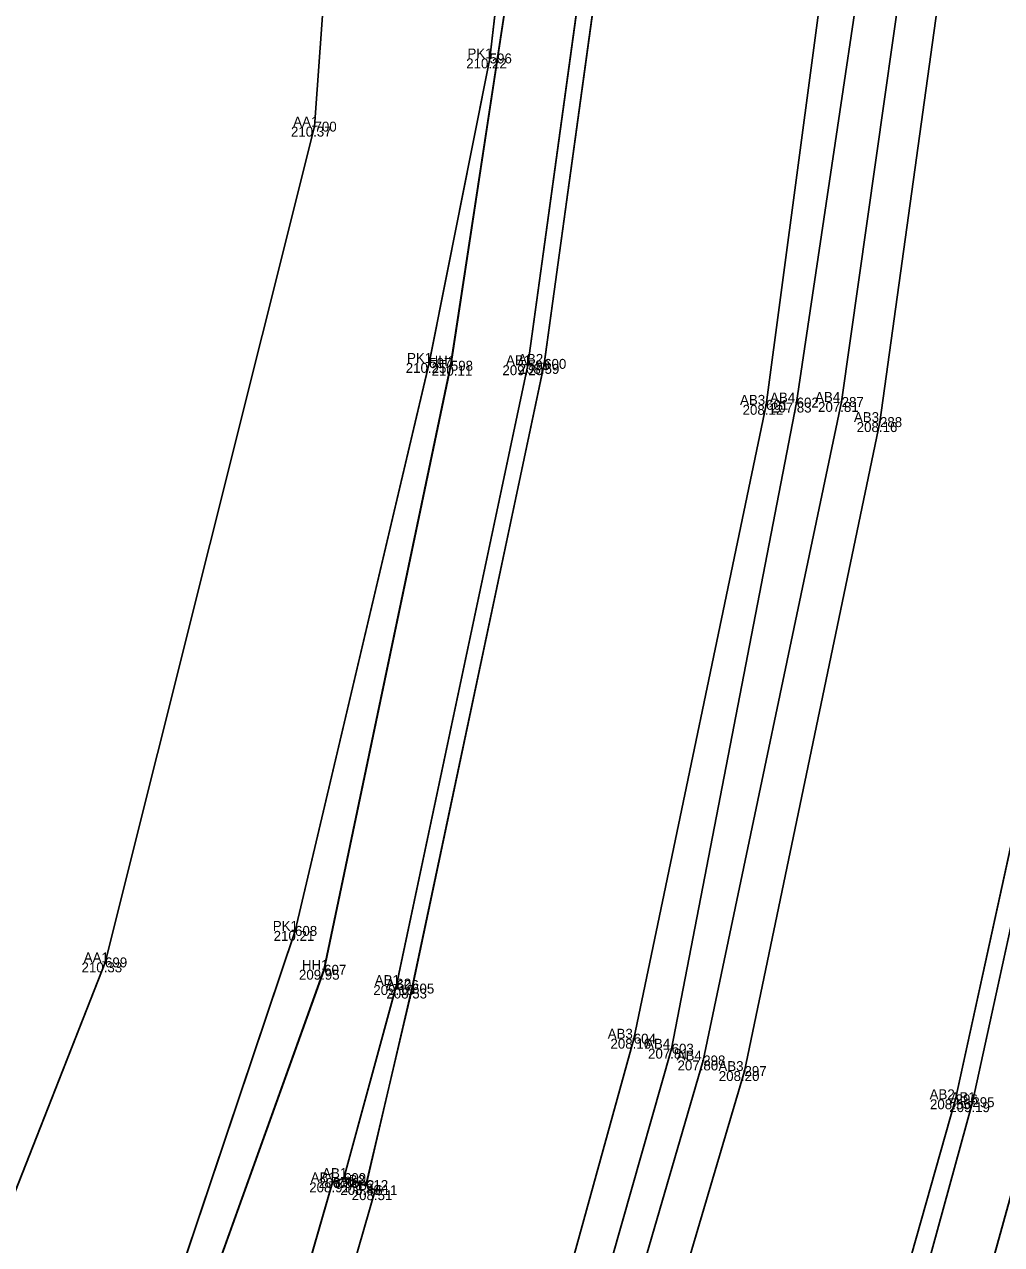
# Model space of a CAD drawing. Extents: x -263091 to -262565, y -1238731 to -1237092.
# Drawn here: x -262851.71 to -262832.04, y -1238071.97 to -1238047.41 of the extents above; entities that cross this region are included whole.
import ezdxf

# ---------------------------------------------------------------- set-up
doc = ezdxf.new("R2010")
doc.units = 0
for name, color, linetype in [('01_Hrana_betónu', 7, 'Continuous'), ('02_Oplotenie', 7, 'Continuous'), ('03_Asfalt', 7, 'Continuous'), ('05_Hrana_terénu', 7, 'Continuous'), ('09_Múrik', 7, 'Continuous'), ('Groma (21)', 7, 'Continuous'), ('Groma (22)', 7, 'Continuous'), ('Groma (23)', 7, 'Continuous'), ('Groma (24)', 7, 'Continuous'), ('U003_Betónové_múriky', 7, 'Continuous'), ('U003_Betónové_panely', 7, 'Continuous'), ('U003_Zeleň_mimo', 7, 'Continuous'), ('U003_Zeleň_vnútro', 7, 'Continuous'), ('U003_Zeleň_zatrávňovač', 7, 'Continuous'), ('U005_Betóny_prídavné', 7, 'Continuous')]:
    doc.layers.add(name, color=color, linetype=linetype)

msp = doc.modelspace()

# ---------------------------------------------------------------- linework, layer by layer
at = {"layer": '01_Hrana_betónu'}
for points in [[(-262903.088, -1238238.797), (-262890.817, -1238204.479), (-262885.468, -1238189.492), (-262878.003, -1238168.56), (-262870.455, -1238147.513), (-262864.947, -1238132.168), (-262859.037, -1238116.651), (-262848.977, -1238095.826), (-262842.353, -1238078.361), (-262839.446, -1238067.823), (-262836.783, -1238055.069), (-262834.905, -1238040.999), (-262833.763, -1238025.462), (-262832.297, -1238000.555), (-262831.13, -1237981.111), (-262829.791, -1237958.391), (-262828.651, -1237937.03), (-262828.571, -1237935.876)], [(-262827.762, -1237935.927), (-262827.853, -1237937.062), (-262829.049, -1237958.415), (-262830.305, -1237981.211), (-262831.433, -1238000.629), (-262832.987, -1238025.43), (-262834.086, -1238041.027), (-262836.169, -1238055.023), (-262838.684, -1238068.024), (-262841.681, -1238078.569), (-262848.285, -1238096.308), (-262858.162, -1238116.913), (-262863.876, -1238132.122), (-262869.919, -1238147.692), (-262877.244, -1238168.638), (-262884.69, -1238189.67), (-262901.991, -1238238.762)], [(-262827.034, -1237935.973), (-262827.072, -1237937.036), (-262828.491, -1237960.168), (-262829.643, -1237980.454), (-262830.754, -1238002.123), (-262832.4, -1238026.024), (-262833.369, -1238041.644), (-262835.263, -1238055.011), (-262838.048, -1238068.261), (-262841.826, -1238081.232), (-262846.645, -1238094.136), (-262857.777, -1238117.273), (-262863.292, -1238131.948), (-262884.082, -1238190.299), (-262901.352, -1238238.742)], [(-262900.376, -1238238.711), (-262890.192, -1238209.46), (-262883.463, -1238190.564), (-262868.512, -1238148.877), (-262862.514, -1238132.276), (-262857.014, -1238117.706), (-262845.846, -1238094.561), (-262841.058, -1238081.49), (-262837.218, -1238068.474), (-262834.492, -1238055.416), (-262832.606, -1238041.772), (-262831.509, -1238026.143), (-262830.024, -1238002.24), (-262828.826, -1237980.518), (-262827.576, -1237960.277), (-262826.117, -1237937.218), (-262826.079, -1237936.033)], [(-262908.762, -1238238.978), (-262904.818, -1238227.708), (-262897.756, -1238208.088), (-262895.676, -1238202.213), (-262890.59, -1238187.74), (-262883.178, -1238166.691), (-262875.605, -1238145.524), (-262870.177, -1238130.111), (-262864.546, -1238115.411), (-262863.698, -1238113.971), (-262862.86, -1238112.208), (-262862.02, -1238109.736), (-262852.529, -1238091.409), (-262847.756, -1238078.518), (-262845.507, -1238070.714), (-262845.277, -1238070.627)], [(-262907.715, -1238238.945), (-262903.959, -1238228.072), (-262896.871, -1238208.378), (-262894.873, -1238202.609), (-262889.743, -1238188.028), (-262882.328, -1238167.085), (-262874.744, -1238145.867), (-262869.274, -1238130.427), (-262863.367, -1238114.899), (-262851.765, -1238091.959), (-262846.929, -1238078.783), (-262844.647, -1238070.871), (-262844.833, -1238070.767)]]:
    msp.add_lwpolyline(points, dxfattribs=at)
at = {"layer": '02_Oplotenie'}
msp.add_lwpolyline([(-262912.451, -1238238.295), (-262908.254, -1238226.663), (-262901.526, -1238207.942), (-262898.552, -1238199.602), (-262894.22, -1238186.327), (-262886.794, -1238165.648), (-262879.297, -1238144.201), (-262873.976, -1238128.814), (-262867.141, -1238113.572), (-262855.316, -1238089.931), (-262850.675, -1238078.807), (-262846.261, -1238065.654), (-262843.56, -1238054.226), (-262842.344, -1238048.099), (-262841.445, -1238040.349), (-262840.733, -1238030.077), (-262839.013, -1238000.384), (-262838.353, -1237989.712), (-262835.178, -1237935.879)], dxfattribs=at)
at = {"layer": '03_Asfalt'}
msp.add_lwpolyline([(-262912.678, -1238239.103), (-262913.356, -1238239.285), (-262915.717, -1238239.279), (-262916.328, -1238238.784), (-262916.575, -1238236.319), (-262915.768, -1238233.661), (-262912.404, -1238225.097), (-262904.805, -1238205.606), (-262896.687, -1238184.948), (-262888.478, -1238163.929), (-262880.124, -1238142.63), (-262874.65, -1238128.675), (-262868.549, -1238113.075), (-262858.861, -1238088.481), (-262853.132, -1238074.038), (-262850.084, -1238066.288), (-262845.869, -1238049.471), (-262845.094, -1238038.662), (-262844.346, -1238028.542), (-262842.599, -1238000.955), (-262841.603, -1237985.168), (-262838.824, -1237943.888), (-262838.24, -1237934.633), (-262838.283, -1237933.488)], dxfattribs=at)
at = {"layer": '05_Hrana_terénu'}
for points in [[(-262835.062, -1237935.275), (-262834.86, -1237936.333), (-262838.087, -1237989.633), (-262838.484, -1238000.332), (-262840.387, -1238030.181), (-262840.991, -1238040.253), (-262843.126, -1238054.282), (-262845.675, -1238066.436), (-262850.413, -1238079.623), (-262854.798, -1238090.209), (-262863.856, -1238108.78), (-262866.643, -1238114.502), (-262872.333, -1238129.41), (-262877.981, -1238144.625), (-262885.616, -1238166.033), (-262893.121, -1238186.676), (-262898.244, -1238201.149), (-262900.554, -1238208.001), (-262907.375, -1238226.781), (-262911.85, -1238238.364), (-262912.678, -1238239.103)], [(-262849.564, -1238120.544), (-262839.894, -1238095.583), (-262835.301, -1238083.403), (-262831.402, -1238069.334), (-262828.632, -1238056.516), (-262826.436, -1238041.83), (-262825.08, -1238026.06), (-262823.863, -1238001.967), (-262822.633, -1237980.847), (-262821.298, -1237960.54), (-262820.334, -1237939.047), (-262819.871, -1237937.657)]]:
    msp.add_lwpolyline(points, dxfattribs=at)
at = {"layer": '09_Múrik'}
for points in [[(-262845.277, -1238070.627), (-262844.218, -1238066.744), (-262841.577, -1238054.272), (-262839.647, -1238040.289), (-262838.75, -1238030.675), (-262836.979, -1238000.411), (-262836.237, -1237989.843), (-262834.391, -1237956.949), (-262833.055, -1237935.594)], [(-262844.833, -1238070.767), (-262843.906, -1238066.814), (-262841.249, -1238054.245), (-262839.306, -1238040.158), (-262838.493, -1238030.433), (-262836.614, -1238000.277), (-262836.049, -1237989.856), (-262833.996, -1237956.678), (-262832.67, -1237935.618)], [(-262840.924, -1238094.827), (-262836.941, -1238083.068), (-262832.969, -1238069.042), (-262830.214, -1238056.416), (-262828.063, -1238041.942), (-262826.83, -1238026.465), (-262825.494, -1238001.855), (-262824.316, -1237980.84), (-262823.031, -1237960.337), (-262821.719, -1237936.336)], [(-262840.6, -1238094.732), (-262836.43, -1238082.967), (-262832.633, -1238069.1), (-262829.86, -1238056.421), (-262827.688, -1238042.018), (-262826.338, -1238026.448), (-262825.108, -1238001.872), (-262823.89, -1237980.741), (-262822.602, -1237960.47), (-262821.253, -1237936.39)]]:
    msp.add_lwpolyline(points, dxfattribs=at)
at = {"layer": 'Groma (21)'}
for centre in [(-262842.344, -1238048.099), (-262845.869, -1238049.471), (-262843.56, -1238054.226), (-262841.249, -1238054.245), (-262843.126, -1238054.282), (-262841.577, -1238054.272), (-262836.783, -1238055.069), (-262836.169, -1238055.023), (-262835.263, -1238055.011), (-262834.492, -1238055.416), (-262846.261, -1238065.654), (-262850.084, -1238066.288), (-262845.675, -1238066.436), (-262844.218, -1238066.744), (-262843.906, -1238066.814), (-262839.446, -1238067.823), (-262838.684, -1238068.024), (-262838.048, -1238068.261), (-262837.218, -1238068.474), (-262832.969, -1238069.042), (-262832.633, -1238069.1), (-262845.507, -1238070.714), (-262845.277, -1238070.627), (-262844.833, -1238070.767), (-262844.647, -1238070.871)]:
    msp.add_circle(centre, 0.01, dxfattribs=at)
at = {"layer": 'U003_Betónové_múriky'}
for points in [[(-262834.39, -1237956.95), (-262833.05, -1237935.59), (-262832.67, -1237935.62), (-262834, -1237956.68), (-262836.05, -1237989.86), (-262836.61, -1238000.28), (-262838.49, -1238030.43), (-262839.31, -1238040.16), (-262841.25, -1238054.25), (-262843.91, -1238066.81), (-262844.83, -1238070.77), (-262845.28, -1238070.63), (-262844.22, -1238066.74), (-262841.58, -1238054.27), (-262839.65, -1238040.29), (-262838.75, -1238030.68), (-262836.98, -1238000.41), (-262836.24, -1237989.84)], [(-262821.25, -1237936.39), (-262822.6, -1237960.47), (-262823.89, -1237980.74), (-262825.11, -1238001.87), (-262826.34, -1238026.45), (-262827.69, -1238042.02), (-262829.86, -1238056.42), (-262832.63, -1238069.1), (-262836.43, -1238082.97), (-262840.6, -1238094.73), (-262840.92, -1238094.83), (-262836.94, -1238083.07), (-262832.97, -1238069.04), (-262830.21, -1238056.42), (-262828.06, -1238041.94), (-262826.83, -1238026.47), (-262825.49, -1238001.86), (-262824.32, -1237980.84), (-262823.03, -1237960.34), (-262821.72, -1237936.34)]]:
    msp.add_lwpolyline(points, close=True, dxfattribs=at)
for points in [[(-262836.24, -1237989.84), (-262834.39, -1237956.95), (-262833.05, -1237935.59), (-262832.67, -1237935.62), (-262834, -1237956.68), (-262836.05, -1237989.86), (-262836.61, -1238000.28), (-262838.49, -1238030.43), (-262839.31, -1238040.16), (-262841.25, -1238054.25), (-262843.91, -1238066.81), (-262844.83, -1238070.77), (-262845.28, -1238070.63), (-262844.22, -1238066.74), (-262841.58, -1238054.27), (-262839.65, -1238040.29), (-262838.75, -1238030.68), (-262836.98, -1238000.41), (-262836.24, -1237989.84)], [(-262821.72, -1237936.34), (-262821.25, -1237936.39), (-262822.6, -1237960.47), (-262823.89, -1237980.74), (-262825.11, -1238001.87), (-262826.34, -1238026.45), (-262827.69, -1238042.02), (-262829.86, -1238056.42), (-262832.63, -1238069.1), (-262836.43, -1238082.97), (-262840.6, -1238094.73), (-262840.92, -1238094.83), (-262836.94, -1238083.07), (-262832.97, -1238069.04), (-262830.21, -1238056.42), (-262828.06, -1238041.94), (-262826.83, -1238026.47), (-262825.49, -1238001.86), (-262824.32, -1237980.84), (-262823.03, -1237960.34), (-262821.72, -1237936.34)]]:
    msp.add_lwpolyline(points, dxfattribs=at)
at = {"layer": 'U003_Betónové_panely'}
for points in [[(-262863.7, -1238113.97), (-262862.86, -1238112.21), (-262862.02, -1238109.74), (-262852.53, -1238091.41), (-262847.76, -1238078.52), (-262845.51, -1238070.71), (-262845.28, -1238070.63), (-262844.83, -1238070.77), (-262843.91, -1238066.81), (-262841.25, -1238054.25), (-262839.31, -1238040.16), (-262838.49, -1238030.43), (-262836.61, -1238000.28), (-262836.05, -1237989.86), (-262834, -1237956.68), (-262832.67, -1237935.62), (-262832.64, -1237935.62), (-262832.51, -1237933.84)], [(-262863.7, -1238113.97), (-262862.86, -1238112.21), (-262862.02, -1238109.74), (-262852.53, -1238091.41), (-262847.76, -1238078.52), (-262845.51, -1238070.71), (-262845.28, -1238070.63), (-262844.83, -1238070.77), (-262843.91, -1238066.81), (-262841.25, -1238054.25), (-262839.31, -1238040.16), (-262838.49, -1238030.43), (-262836.61, -1238000.28), (-262836.05, -1237989.86), (-262834, -1237956.68), (-262832.67, -1237935.62), (-262832.64, -1237935.62), (-262832.51, -1237933.84)], [(-262822, -1237934.47), (-262822.23, -1237936.28), (-262821.72, -1237936.34), (-262823.03, -1237960.34), (-262824.32, -1237980.84), (-262825.49, -1238001.86), (-262826.83, -1238026.47), (-262828.06, -1238041.94), (-262830.21, -1238056.42), (-262832.97, -1238069.04), (-262836.94, -1238083.07), (-262840.92, -1238094.83), (-262840.6, -1238094.73), (-262841.76, -1238095.81), (-262851.46, -1238119.84), (-262857.2, -1238134.12), (-262863.32, -1238150.73), (-262871.41, -1238173.11), (-262878.16, -1238192.14), (-262884.61, -1238210.94), (-262889.86, -1238225.24), (-262892.75, -1238232.5), (-262895.19, -1238238.55), (-262900.83, -1238252.4)], [(-262822, -1237934.47), (-262822.23, -1237936.28), (-262821.72, -1237936.34), (-262823.03, -1237960.34), (-262824.32, -1237980.84), (-262825.49, -1238001.86), (-262826.83, -1238026.47), (-262828.06, -1238041.94), (-262830.21, -1238056.42), (-262832.97, -1238069.04), (-262836.94, -1238083.07), (-262840.92, -1238094.83), (-262840.6, -1238094.73), (-262841.76, -1238095.81), (-262851.46, -1238119.84), (-262857.2, -1238134.12), (-262863.32, -1238150.73), (-262871.41, -1238173.11), (-262878.16, -1238192.14), (-262884.61, -1238210.94), (-262889.86, -1238225.24), (-262892.75, -1238232.5), (-262895.19, -1238238.55), (-262900.83, -1238252.4)]]:
    msp.add_lwpolyline(points, dxfattribs=at)
at = {"layer": 'U003_Zeleň_mimo'}
for points in [[(-262868.55, -1238113.08), (-262858.86, -1238088.48), (-262853.13, -1238074.04), (-262850.08, -1238066.29), (-262845.87, -1238049.47), (-262845.09, -1238038.66), (-262844.35, -1238028.54), (-262842.6, -1238000.96), (-262841.6, -1237985.17), (-262838.82, -1237943.89), (-262838.24, -1237934.63)], [(-262836.32, -1237934.59), (-262836.29, -1237935.17), (-262835.06, -1237935.28), (-262835.18, -1237935.88), (-262838.35, -1237989.71), (-262839.01, -1238000.38), (-262840.73, -1238030.08), (-262841.45, -1238040.35), (-262842.34, -1238048.1), (-262843.56, -1238054.23), (-262846.26, -1238065.65), (-262850.68, -1238078.81), (-262855.32, -1238089.93), (-262867.14, -1238113.57)]]:
    msp.add_lwpolyline(points, dxfattribs=at)
at = {"layer": 'U003_Zeleň_vnútro'}
for points in [[(-262849.56, -1238120.54), (-262839.89, -1238095.58), (-262835.3, -1238083.4), (-262831.4, -1238069.33), (-262828.63, -1238056.52), (-262826.44, -1238041.83), (-262825.08, -1238026.06), (-262823.86, -1238001.97), (-262822.63, -1237980.85), (-262821.3, -1237960.54), (-262820.33, -1237939.05), (-262819.87, -1237937.66), (-262819.76, -1237938.03), (-262820.79, -1237960.68), (-262821.84, -1237980.92), (-262823.31, -1238002.11), (-262824.58, -1238026.07), (-262825.82, -1238041.97), (-262827.77, -1238056.55), (-262830.57, -1238069.55), (-262834.59, -1238083.86), (-262839.33, -1238095.84), (-262848.78, -1238120.94)], [(-262849.56, -1238120.54), (-262839.89, -1238095.58), (-262835.3, -1238083.4), (-262831.4, -1238069.33), (-262828.63, -1238056.52), (-262826.44, -1238041.83), (-262825.08, -1238026.06), (-262823.86, -1238001.97), (-262822.63, -1237980.85), (-262821.3, -1237960.54), (-262820.33, -1237939.05), (-262819.87, -1237937.66), (-262819.76, -1237938.03), (-262820.79, -1237960.68), (-262821.84, -1237980.92), (-262823.31, -1238002.11), (-262824.58, -1238026.07), (-262825.82, -1238041.97), (-262827.77, -1238056.55), (-262830.57, -1238069.55), (-262834.59, -1238083.86), (-262839.33, -1238095.84), (-262848.78, -1238120.94)], [(-262867.14, -1238113.57), (-262855.32, -1238089.93), (-262850.68, -1238078.81), (-262846.26, -1238065.65), (-262843.56, -1238054.23), (-262842.34, -1238048.1), (-262841.45, -1238040.35), (-262840.73, -1238030.08), (-262839.01, -1238000.38)], [(-262867.14, -1238113.57), (-262855.32, -1238089.93), (-262850.68, -1238078.81), (-262846.26, -1238065.65), (-262843.56, -1238054.23), (-262842.34, -1238048.1), (-262841.45, -1238040.35), (-262840.73, -1238030.08), (-262839.01, -1238000.38)], [(-262838.48, -1238000.33), (-262840.39, -1238030.18), (-262840.99, -1238040.25), (-262843.13, -1238054.28), (-262845.68, -1238066.44), (-262850.41, -1238079.62), (-262854.8, -1238090.21), (-262863.86, -1238108.78), (-262863.4, -1238109.07), (-262864.42, -1238111.37), (-262865.55, -1238113.22)], [(-262838.48, -1238000.33), (-262840.39, -1238030.18), (-262840.99, -1238040.25), (-262843.13, -1238054.28), (-262845.68, -1238066.44), (-262850.41, -1238079.62), (-262854.8, -1238090.21), (-262863.86, -1238108.78), (-262863.4, -1238109.07), (-262864.42, -1238111.37), (-262865.55, -1238113.22)]]:
    msp.add_lwpolyline(points, dxfattribs=at)
at = {"layer": 'U003_Zeleň_zatrávňovač'}
for points in [[(-262836.98, -1238000.41), (-262838.75, -1238030.68), (-262839.65, -1238040.29), (-262841.58, -1238054.27), (-262844.22, -1238066.74), (-262845.28, -1238070.63), (-262845.51, -1238070.71), (-262847.76, -1238078.52), (-262852.53, -1238091.41), (-262862.02, -1238109.74), (-262863.4, -1238109.07), (-262863.86, -1238108.78), (-262854.8, -1238090.21), (-262850.41, -1238079.62), (-262845.68, -1238066.44), (-262843.13, -1238054.28), (-262840.99, -1238040.25), (-262840.39, -1238030.18), (-262838.48, -1238000.33)], [(-262862.02, -1238109.74), (-262863.4, -1238109.07), (-262863.86, -1238108.78), (-262854.8, -1238090.21), (-262850.41, -1238079.62), (-262845.68, -1238066.44), (-262843.13, -1238054.28), (-262840.99, -1238040.25), (-262840.39, -1238030.18), (-262838.48, -1238000.33)], [(-262836.98, -1238000.41), (-262838.75, -1238030.68), (-262839.65, -1238040.29), (-262841.58, -1238054.27), (-262844.22, -1238066.74), (-262845.28, -1238070.63), (-262845.51, -1238070.71), (-262847.76, -1238078.52), (-262852.53, -1238091.41), (-262862.02, -1238109.74)], [(-262851.46, -1238119.84), (-262841.76, -1238095.81), (-262840.6, -1238094.73), (-262836.43, -1238082.97), (-262832.63, -1238069.1), (-262829.86, -1238056.42), (-262827.69, -1238042.02), (-262826.34, -1238026.45), (-262825.11, -1238001.87)], [(-262823.86, -1238001.97), (-262825.08, -1238026.06), (-262826.44, -1238041.83), (-262828.63, -1238056.52), (-262831.4, -1238069.33), (-262835.3, -1238083.4), (-262839.89, -1238095.58), (-262849.56, -1238120.54)]]:
    msp.add_lwpolyline(points, dxfattribs=at)
at = {"layer": 'U005_Betóny_prídavné'}
for points in [[(-262851.46, -1238119.84), (-262841.76, -1238095.81), (-262840.6, -1238094.73), (-262836.43, -1238082.97), (-262832.63, -1238069.1), (-262829.86, -1238056.42), (-262827.69, -1238042.02), (-262826.34, -1238026.45), (-262825.11, -1238001.87)], [(-262823.86, -1238001.97), (-262825.08, -1238026.06), (-262826.44, -1238041.83), (-262828.63, -1238056.52), (-262831.4, -1238069.33), (-262835.3, -1238083.4), (-262839.89, -1238095.58), (-262849.56, -1238120.54)]]:
    msp.add_lwpolyline(points, dxfattribs=at)

# ---------------------------------------------------------------- texts
at = {"layer": 'Groma (22)'}
for s, p in [('596', (-262842.344, -1238048.199)), ('700', (-262845.869, -1238049.571)), ('597', (-262843.56, -1238054.326)), ('598', (-262843.126, -1238054.382)), ('599', (-262841.577, -1238054.372)), ('600', (-262841.249, -1238054.345)), ('601', (-262836.783, -1238055.169)), ('602', (-262836.169, -1238055.123)), ('287', (-262835.263, -1238055.111)), ('288', (-262834.492, -1238055.516)), ('608', (-262846.261, -1238065.754)), ('699', (-262850.084, -1238066.388)), ('607', (-262845.675, -1238066.536)), ('606', (-262844.218, -1238066.844)), ('605', (-262843.906, -1238066.914)), ('604', (-262839.446, -1238067.923)), ('603', (-262838.684, -1238068.124)), ('298', (-262838.048, -1238068.361)), ('297', (-262837.218, -1238068.574)), ('296', (-262832.969, -1238069.142)), ('295', (-262832.633, -1238069.2)), ('610', (-262845.507, -1238070.814)), ('609', (-262845.277, -1238070.727)), ('612', (-262844.833, -1238070.867)), ('611', (-262844.647, -1238070.971))]:
    msp.add_text(s, height=0.2, dxfattribs=at).set_placement(p)
at = {"layer": 'Groma (23)'}
for s, p in [('210.22', (-262842.817, -1238048.299)), ('210.37', (-262846.343, -1238049.671)), ('210.25', (-262844.033, -1238054.426)), ('208.59', (-262841.761, -1238054.445)), ('210.11', (-262843.513, -1238054.482)), ('209.20', (-262842.088, -1238054.472)), ('208.12', (-262837.256, -1238055.269)), ('207.83', (-262836.686, -1238055.223)), ('207.81', (-262835.737, -1238055.211)), ('208.16', (-262834.96, -1238055.616)), ('210.21', (-262846.691, -1238065.854)), ('210.33', (-262850.557, -1238066.488)), ('209.95', (-262846.182, -1238066.636)), ('209.18', (-262844.686, -1238066.944)), ('208.53', (-262844.423, -1238067.014)), ('208.16', (-262839.914, -1238068.023)), ('207.81', (-262839.158, -1238068.224)), ('207.80', (-262838.565, -1238068.461)), ('208.20', (-262837.734, -1238068.674)), ('208.55', (-262833.486, -1238069.242)), ('209.19', (-262833.097, -1238069.3)), ('208.91', (-262845.975, -1238070.914)), ('208.90', (-262845.788, -1238070.827)), ('208.49', (-262845.35, -1238070.967)), ('208.51', (-262845.12, -1238071.071))]:
    msp.add_text(s, height=0.2, dxfattribs=at).set_placement(p)
at = {"layer": 'Groma (24)'}
for s, p in [('PK1', (-262842.791, -1238048.099)), ('AA1', (-262846.297, -1238049.471)), ('PK1', (-262844.007, -1238054.226)), ('HH1', (-262843.573, -1238054.282)), ('AB1', (-262842.015, -1238054.272)), ('AB2', (-262841.773, -1238054.245)), ('AB3', (-262837.307, -1238055.069)), ('AB4', (-262836.703, -1238055.023)), ('AB4', (-262835.797, -1238055.011)), ('AB3', (-262835.016, -1238055.416)), ('PK1', (-262846.708, -1238065.654)), ('AA1', (-262850.512, -1238066.288)), ('HH1', (-262846.122, -1238066.436)), ('AB1', (-262844.656, -1238066.744)), ('AB2', (-262844.43, -1238066.814)), ('AB3', (-262839.97, -1238067.823)), ('AB4', (-262839.218, -1238068.024)), ('AB4', (-262838.582, -1238068.261)), ('AB3', (-262837.742, -1238068.474)), ('AB2', (-262833.493, -1238069.042)), ('AB1', (-262833.071, -1238069.1)), ('AB1', (-262845.715, -1238070.627)), ('AB1', (-262845.945, -1238070.714)), ('AB2', (-262845.357, -1238070.767)), ('AB2', (-262845.171, -1238070.871))]:
    msp.add_text(s, height=0.2, dxfattribs=at).set_placement(p)

doc.saveas('drawing.dxf')
